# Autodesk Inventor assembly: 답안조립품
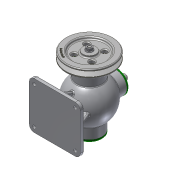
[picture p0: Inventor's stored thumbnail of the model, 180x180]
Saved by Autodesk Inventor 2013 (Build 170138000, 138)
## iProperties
Created: 2018-06
Part Number: 답안조립품
Document SubType Name: Assembly
Designer: Administrator
Author: Administrator
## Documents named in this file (19)
- C:\Users\Administrator\Desktop\480612V1005\답안조립품.iam
- C:\Users\Administrator\Desktop\480612V1005\본체.ipt
- C:\Users\Administrator\Desktop\480612V1005\V-벨트풀리.ipt
- C:\Users\Administrator\Desktop\480612V1005\너트 M8.ipt
- C:\Users\Administrator\Desktop\480612V1005\뒤커버.ipt
- C:\Users\Administrator\Desktop\480612V1005\멈춤링 15x1.ipt
- C:\Users\Administrator\Desktop\480612V1005\멈춤링 35x1.6.ipt
- 멈춤링 35x1.6.ipt
- C:\Users\Administrator\Desktop\480612V1005\베어링 6202.ipt
- 베어링 6202.ipt
- C:\Users\Administrator\Desktop\480612V1005\볼트 M4x12.ipt
- C:\Users\Administrator\Desktop\480612V1005\볼트 M4x16.ipt
- C:\Users\Administrator\Desktop\480612V1005\부시.ipt
- C:\Users\Administrator\Desktop\480612V1005\상부커버.ipt
- C:\Users\Administrator\Desktop\480612V1005\슬라이드.ipt
- C:\Users\Administrator\Desktop\480612V1005\앞커버.ipt
- C:\Users\Administrator\Desktop\480612V1005\오일 실 15 30 7.ipt
- C:\Users\Administrator\Desktop\480612V1005\키 4x4x12.ipt
- C:\Users\Administrator\Desktop\480612V1005\편심축.ipt
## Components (1 placed, 1 different names)
1. V-벨트풀리:1
